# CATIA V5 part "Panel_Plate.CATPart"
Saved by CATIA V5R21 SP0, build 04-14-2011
Part number: LCD.1
Bounding box of the stored display mesh (mm): x -92.6 to 92.6, y -50 to 50, z 0 to 2.8
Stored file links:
  C:\Users\Pouria\Desktop\Box\Assembled\Panel_Plate.CATPart
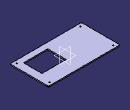
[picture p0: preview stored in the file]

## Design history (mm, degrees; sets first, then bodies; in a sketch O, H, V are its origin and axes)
Body1 (main body)
  Sketch1 on xy-plane, origin (0, 0, 0), H (1, 0, 0), V (0, 1, 0)
    line L1 (92.8, 50) -> (92.8, 20)
    line L2 (92.8, -50) -> (-92.8, -50)
    line L3 (-92.8, -50) -> (-92.8, -20)
    line L4 (-92.8, 50) -> (92.8, 50)
    point P1 (92.8, 50)
    point P2 (92.8, -50)
    line L5 (9.8, 13) -> (72.8, 13)
    line L6 (72.8, 13) -> (72.8, -35)
    line L7 (72.8, -35) -> (9.8, -35)
    line L8 (9.8, -35) -> (9.8, 13)
    line L9 (92.8, 20) -> (90, 20)
    line L10 (90, 20) -> (90, -20)
    line L11 (90, -20) -> (92.8, -20)
    point P12 (92.8, -20)
    point P13 (-92.8, 20)
    line L12 (-92.8, 20) -> (-90, 20)
    line L13 (-90, 20) -> (-90, -20)
    line L14 (-90, -20) -> (-92.8, -20)
    line L15 (92.8, -20) -> (92.8, -50)
    line L16 (-92.8, 20) -> (-92.8, 50)
    circle A1 centre (82.5, -42.5) radius 1.5
    point P17 (82.5, -42.5)
    circle A2 centre (82.5, 42.5) radius 1.5
    point P18 (82.5, 42.5)
    circle A3 centre (-82.5, 42.5) radius 1.5
    point P19 (-82.5, 42.5)
    circle A4 centre (-82.5, -42.5) radius 1.5
    point P20 (-82.5, -42.5)
    length L4 = 185.6
    length L5 = 63
    length L6 = 48
    distance L2 L7 = 15
    length L9 = 2.8
    length L13 = 40
    distance P1 P2 = 100
    distance L1 L6 = 20
    distance P17 L2 = 7.5
    distance P17 L10 = 7.5
    distance P20 L13 = 7.5
    distance P20 L2 = 7.5
    distance P19 L4 = 7.5
    distance P19 L13 = 7.5
    distance P18 L4 = 7.5
    distance P18 L10 = 7.5
    radius A2 = 1.5
    radius A3 = 1.5
    radius A4 = 1.5
    radius A1 = 1.5
    vertical: L1 V, L3 V, L6 V, L8 V, L10 V, L13 V, L15 V, L16 V
    horizontal: L2 H, L4 H, L5 H, L7 H, L9 H, L11 H, L12 H, L14 H
    equidistance: L1 L3 O, L2 L4 O
    coincidence: P12 L1, P13 L3, L9 L12, L11 L14, L1 L15, L3 L16
    symmetry: L12 L14 H, L11 L9 H, L10 L13 V
  Pad1: profile Sketch1, direction (0, 0, 1), length 2.8
  Sketch2 on end face of Pad1, origin (0, 0, 2.8), H (1, 0, 0), V (0, 1, 0)
    circle A1 centre (76.55, -33.1) radius 1.6
    point P1 (76.55, -33.1)
    circle A2 centre (0.65, -33.1) radius 1.6
    point P2 (0.65, -33.1)
    circle A3 centre (0.65, 11.1) radius 1.6
    point P3 (0.65, 11.1)
    circle A4 centre (76.55, 11.1) radius 1.6
    point P4 (76.55, 11.1)
    radius A4 = 1.6
    radius A1 = 1.6
    radius A3 = 1.6
    radius A2 = 1.6
    distance P3 V = 0.65
    distance P3 H = 11.1
    distance P2 V = 0.65
    distance P2 H = 33.1
    distance P1 V = 76.55
    distance P1 H = 33.1
    distance P4 V = 76.55
    distance P4 H = 11.1
  Pocket1: profile Sketch2, direction (0, 0, -1), through (limit type 6)
  Sketch3 on end face of Pad1, origin (0, 0, 2.8), H (1, 0, 0), V (0, 1, 0)
    line L1 (72.8, 25.4528) -> (92.8, 25.4528)
    line L2 (92.8, 25.4528) -> (92.8, -36.367)
    line L3 (92.8, -36.367) -> (72.8, -36.367)
    line L4 (72.8, -36.367) -> (72.8, 25.4528)
    line L5 (9.8, -37.5525) -> (-92.8, -37.5525)
    line L6 (-92.8, -37.5525) -> (-92.8, 31.2114)
    line L7 (-92.8, 31.2114) -> (9.8, 31.2114)
    line L8 (9.8, 31.2114) -> (9.8, -37.5525)
    reference projected line E1 (92.8, 20) -> (92.8, 50) from edge [face of Pad1 from Sketch1.L1 | end face of Pad1]
    reference projected line E2 (72.8, -35) -> (72.8, 13) from edge [end face of Pad1 | face of Pad1 from Sketch1.L6]
    reference projected line E3 (9.8, 13) -> (9.8, -35) from edge [end face of Pad1 | face of Pad1 from Sketch1.L8]
    reference projected line E4 (-92.8, -20) -> (-92.8, -50) from edge [face of Pad1 from Sketch1.L3 | end face of Pad1]
    horizontal: L1 H, L3 H, L5 H, L7 H
    vertical: L2 V, L4 V, L6 V, L8 V
    coincidence: L2 E1, L4 E2, L8 E3, L6 E4
  Pad2: profile Sketch3, direction (0, 0, 1), up to start face of Pad1
  Sketch4 on face of Pad1, origin (0, 0, 2.8), H (1, 0, 0), V (0, 1, 0)
    line L1 (110.9869, 58.4596) -> (92.6, 58.4596)
    line L2 (92.6, 58.4596) -> (92.6, -63.793)
    line L3 (92.6, -63.793) -> (110.9869, -63.793)
    line L4 (110.9869, -63.793) -> (110.9869, 58.4596)
    line L5 (-110.9869, 61.7426) -> (-92.6, 61.7426)
    line L6 (-92.6, 61.7426) -> (-92.6, -53.006)
    line L7 (-92.6, -53.006) -> (-110.9869, -53.006)
    line L8 (-110.9869, -53.006) -> (-110.9869, 61.7426)
    reference projected line E1 (-92.8, -50) -> (-92.8, -20) from edge [face of Pad1 | face of Pad1]
    reference projected line E3 (92.8, -20) -> (92.8, -50) from edge [face of Pad1 | face of Pad1]
    distance L6 E1 = 0.2
    distance L2 E3 = 0.2
    horizontal: L1 H, L3 H, L5 H, L7 H
    vertical: L2 V, L4 V, L6 V, L8 V
  Pocket2: profile Sketch4, direction (0, 0, -1), through (limit type 3)
  Fillet1: radius 2, on edge [face of Pocket2 from Sketch4.L2 | face of Pad1 from Sketch1.L4]; edge [face of Pad1 from Sketch1.L2 | face of Pocket2 from Sketch4.L2]; edge [face of Pocket2 from Sketch4.L6 | face of Pad1 from Sketch1.L2]; edge [face of Pad1 from Sketch1.L4 | face of Pocket2 from Sketch4.L6]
